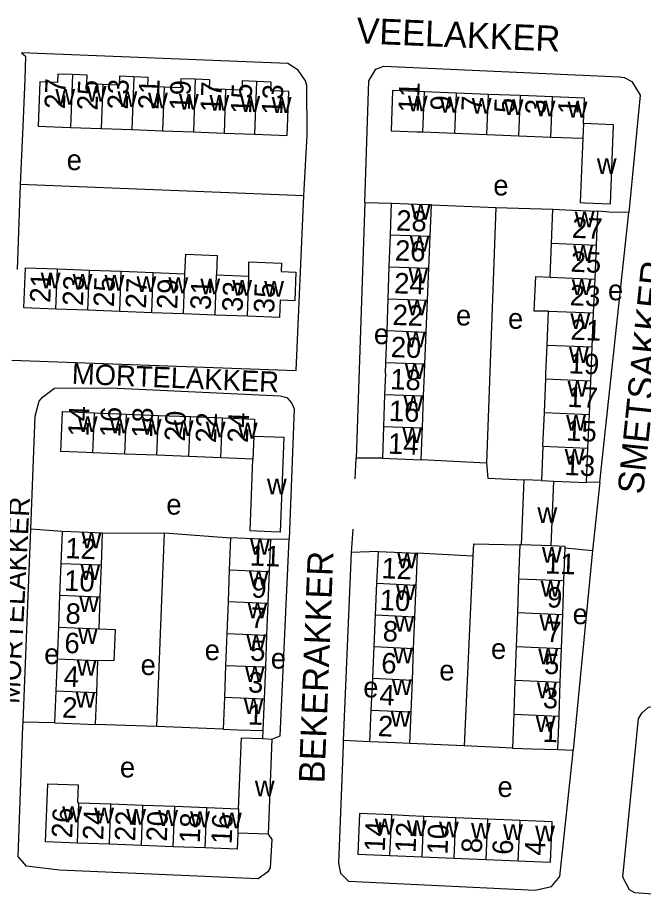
# Model space of a CAD drawing. Extents: x 159675 to 162108, y 386471 to 388472.
# Drawn here: x 161674.3 to 161796.3, y 386647.1 to 386819.4 of the extents above; entities that cross this region are included whole.
import ezdxf

# ---------------------------------------------------------------- set-up
doc = ezdxf.new("R2010")
doc.units = 0
for name, color, linetype in [('BLT_Basislijn', 7, 'Continuous'), ('BLT_Bebouwing', 7, 'Continuous'), ('BLT_Centroide', 7, 'Continuous'), ('BLT_Huisnummer', 7, 'Continuous'), ('BLT_Huisnummer_ tussenligend', 7, 'Continuous'), ('BLT_Onderverdeling_panden', 7, 'Continuous'), ('BLT_Straatnaam', 7, 'Continuous'), ('BLT_Straatnaam_verkleind', 7, 'Continuous')]:
    doc.layers.add(name, color=color, linetype=linetype)

msp = doc.modelspace()

# ---------------------------------------------------------------- linework, layer by layer
at = {"layer": 'BLT_Basislijn'}
for p, q in [((161674.76, 386786.84), (161674.16, 386770.28)), ((161730.1, 386784.65), (161674.76, 386786.84)), ((161741.96, 386783.39), (161740.29, 386733.45)), ((161741.96, 386783.39), (161747.2, 386783.26)), ((161754.96, 386782.93), (161767.51, 386782.36)), ((161767.51, 386782.36), (161765.73, 386732.49)), ((161767.51, 386782.36), (161778.66, 386782.03)), ((161787.79, 386728.78), (161793.47, 386781.38)), ((161740.12, 386729.42), (161740.29, 386733.45)), ((161745.39, 386733.42), (161740.29, 386733.45)), ((161765.73, 386732.49), (161752.95, 386733.14)), ((161787.79, 386728.78), (161785.21, 386728.67)), ((161787.79, 386728.78), (161786.4, 386715.45)), ((161675.32, 386681.93), (161676.8, 386719.59)), ((161682.94, 386719.14), (161676.8, 386719.59)), ((161739.66, 386719.57), (161739.32, 386715.05)), ((161690.77, 386718.83), (161702.9, 386718.89)), ((161701.43, 386681.04), (161702.9, 386718.89)), ((161702.9, 386718.89), (161715.77, 386717.89)), ((161727.24, 386717.62), (161723.65, 386717.55)), ((161763.16, 386716.75), (161763.05, 386714.32)), ((161763.16, 386716.75), (161772.24, 386716.52)), ((161739.32, 386715.05), (161737.76, 386678.31)), ((161744.61, 386715.21), (161739.32, 386715.05)), ((161763.05, 386714.32), (161752.24, 386714.88)), ((161763.05, 386714.32), (161761.38, 386677.29)), ((161781.06, 386715.97), (161786.4, 386715.45)), ((161786.4, 386715.45), (161782.6, 386676.43)), ((161681.46, 386681.8), (161675.32, 386681.93)), ((161701.43, 386681.04), (161689.4, 386681.49)), ((161714.34, 386680.56), (161701.43, 386681.04)), ((161722.06, 386678.7), (161722.13, 386680.26)), ((161742.97, 386678.11), (161737.76, 386678.31)), ((161761.38, 386677.29), (161750.77, 386677.77)), ((161770.77, 386676.86), (161761.38, 386677.29)), ((161779.62, 386676.58), (161782.6, 386676.43))]:
    msp.add_line(p, q, dxfattribs=at)
for points in [[(161675.01, 386812.57), (161675.81, 386811.93), (161675.65, 386807.46), (161675.24, 386798.29), (161674.76, 386786.84)], [(161730.68, 386806.17), (161730.4, 386807.09), (161729, 386809.22), (161726.95, 386810.5), (161675.01, 386812.57)], [(161742.73, 386807.12), (161744.12, 386809.38), (161745.65, 386809.94), (161791.64, 386807.87), (161792.56, 386807.76), (161794.05, 386806.99), (161795.68, 386804.32)], [(161730.1, 386784.65), (161730.72, 386796.47), (161730.68, 386806.17)], [(161741.96, 386783.39), (161742.73, 386807.12)], [(161795.68, 386804.32), (161793.47, 386781.38)], [(161673.12, 386752.56), (161728.61, 386750.56), (161730.1, 386784.65)], [(161793.47, 386781.38), (161789.61, 386781.5), (161787.44, 386781.66)], [(161676.8, 386719.59), (161677.68, 386741.68), (161678.48, 386744.55), (161679.09, 386745.37), (161681.41, 386747.12), (161692.37, 386747.19), (161725.49, 386745.61), (161726.79, 386745.31), (161727.7, 386744.23), (161728.18, 386743.08), (161727.24, 386717.62)], [(161765.73, 386732.49), (161765.98, 386729.53), (161772.97, 386729.2)], [(161723.83, 386678.63), (161725.48, 386679.25), (161727.24, 386717.62)], [(161805.09, 386647.8), (161794.63, 386648.61), (161793.59, 386649.22), (161792.32, 386651.64), (161795.33, 386682.63), (161796.09, 386683.77), (161797.33, 386684.86), (161800.07, 386685.28), (161806.04, 386685.31), (161841.87, 386684), (161847.97, 386683.27), (161849.56, 386681.29), (161849.86, 386679.53), (161849.6, 386649.72), (161849.24, 386648.24), (161847.72, 386646.55), (161844.95, 386646.25), (161810.4, 386647.55)], [(161723.12, 386660.05), (161723.86, 386659.02), (161723.51, 386653.49), (161723.04, 386652.7), (161721.16, 386651.35), (161682.44, 386653.01), (161675.97, 386653.81), (161674.35, 386655.72), (161675.28, 386681.05), (161675.32, 386681.93)], [(161737.76, 386678.31), (161737.73, 386677.52), (161736.81, 386654.37), (161737.21, 386652.44), (161738.8, 386650.88), (161775.17, 386649.12), (161778.39, 386649.83), (161780.04, 386651.8), (161782.52, 386675.55), (161782.6, 386676.43)]]:
    msp.add_lwpolyline(points, dxfattribs=at)
at = {"layer": 'BLT_Bebouwing'}
for p, q in [((161759.86, 386804.72), (161753.63, 386804.97)), ((161766.09, 386804.47), (161759.86, 386804.72)), ((161772.32, 386804.23), (161766.09, 386804.47)), ((161778.56, 386803.98), (161772.32, 386804.23)), ((161684.55, 386798.02), (161690.56, 386797.8)), ((161690.56, 386797.8), (161696.53, 386797.58)), ((161696.53, 386797.58), (161702.53, 386797.35)), ((161702.53, 386797.35), (161708.53, 386797.13)), ((161708.53, 386797.13), (161714.51, 386796.91)), ((161753.32, 386797.13), (161759.55, 386796.88)), ((161714.51, 386796.91), (161720.48, 386796.69)), ((161759.55, 386796.88), (161765.78, 386796.64)), ((161765.78, 386796.64), (161772.01, 386796.39)), ((161772.01, 386796.39), (161778.24, 386796.14)), ((161778.24, 386796.14), (161784.47, 386795.9)), ((161746.98, 386777.04), (161747.2, 386783.26)), ((161754.71, 386776.76), (161754.96, 386782.93)), ((161778.38, 386775.41), (161778.66, 386782.03)), ((161787.16, 386775.04), (161787.44, 386781.66)), ((161746.75, 386770.81), (161746.98, 386777.04)), ((161754.46, 386770.53), (161754.71, 386776.76)), ((161778.1, 386768.79), (161778.38, 386775.41)), ((161786.89, 386768.42), (161787.16, 386775.04)), ((161682.01, 386770.4), (161688.24, 386770.16)), ((161688.24, 386770.16), (161694.47, 386769.93)), ((161694.47, 386769.93), (161700.69, 386769.69)), ((161700.69, 386769.69), (161706.87, 386769.46)), ((161746.52, 386764.58), (161746.75, 386770.81)), ((161754.21, 386764.3), (161754.46, 386770.53)), ((161713.05, 386769.23), (161719.37, 386768.99)), ((161786.61, 386761.8), (161786.89, 386768.42)), ((161746.3, 386758.35), (161746.52, 386764.58)), ((161753.96, 386758.07), (161754.21, 386764.3)), ((161681.72, 386762.55), (161675.49, 386762.78)), ((161687.94, 386762.31), (161681.72, 386762.55)), ((161694.17, 386762.08), (161687.94, 386762.31)), ((161700.4, 386761.85), (161694.17, 386762.08)), ((161706.58, 386761.61), (161700.4, 386761.85)), ((161712.76, 386761.38), (161706.58, 386761.61)), ((161719.08, 386761.14), (161712.76, 386761.38)), ((161777.55, 386755.54), (161777.82, 386762.17)), ((161786.33, 386755.17), (161786.61, 386761.8)), ((161746.07, 386752.12), (161746.3, 386758.35)), ((161753.71, 386751.84), (161753.96, 386758.07)), ((161777.31, 386750), (161777.55, 386755.54)), ((161786.11, 386750), (161786.33, 386755.17)), ((161745.99, 386750), (161746.07, 386752.12)), ((161753.63, 386750), (161753.71, 386751.84)), ((161745.99, 386750), (161745.84, 386745.89)), ((161753.45, 386745.61), (161753.63, 386750)), ((161776.99, 386742.37), (161777.27, 386748.92)), ((161777.27, 386748.92), (161777.31, 386750)), ((161786.05, 386748.55), (161786.11, 386750)), ((161785.77, 386742), (161786.05, 386748.55)), ((161745.84, 386745.89), (161745.62, 386739.66)), ((161753.2, 386739.38), (161753.45, 386745.61)), ((161689.26, 386742.31), (161695.5, 386742.06)), ((161695.5, 386742.06), (161701.74, 386741.81)), ((161776.71, 386735.79), (161776.99, 386742.37)), ((161785.5, 386735.42), (161785.77, 386742)), ((161701.74, 386741.81), (161707.98, 386741.56)), ((161707.98, 386741.56), (161714.23, 386741.31)), ((161745.62, 386739.66), (161745.39, 386733.42)), ((161785.21, 386728.67), (161785.5, 386735.42)), ((161695.19, 386734.26), (161688.94, 386734.51)), ((161701.43, 386734.01), (161695.19, 386734.26)), ((161713.91, 386733.51), (161707.62, 386733.76)), ((161720.15, 386733.26), (161713.91, 386733.51)), ((161745.39, 386733.42), (161752.95, 386733.14)), ((161772.97, 386729.2), (161772.44, 386716.51)), ((161776.43, 386729.06), (161772.97, 386729.2)), ((161778.32, 386716.35), (161778.85, 386728.93)), ((161778.85, 386728.93), (161785.21, 386728.67)), ((161682.94, 386719.14), (161682.69, 386712.91)), ((161690.77, 386718.83), (161690.54, 386712.6)), ((161715.77, 386717.89), (161715.53, 386711.67)), ((161723.4, 386711.36), (161723.65, 386717.55)), ((161772.44, 386716.51), (161772.24, 386716.52)), ((161744.33, 386709.03), (161744.61, 386715.21)), ((161744.61, 386715.21), (161752.24, 386714.88)), ((161780.82, 386709.54), (161781.06, 386715.97)), ((161682.69, 386712.91), (161682.44, 386706.69)), ((161690.54, 386712.6), (161690.31, 386706.38)), ((161715.53, 386711.67), (161715.29, 386705.45)), ((161723.15, 386705.14), (161723.4, 386711.36)), ((161771.98, 386709.91), (161771.74, 386703.3)), ((161780.58, 386702.93), (161780.82, 386709.54)), ((161744.06, 386702.84), (161744.33, 386709.03)), ((161751.74, 386702.51), (161751.99, 386708.69)), ((161682.44, 386706.69), (161682.2, 386700.47)), ((161690.31, 386706.38), (161690.09, 386700.16)), ((161715.29, 386705.45), (161715.06, 386699.23)), ((161722.89, 386698.92), (161723.15, 386705.14)), ((161743.79, 386696.66), (161744.06, 386702.84)), ((161751.5, 386696.32), (161751.74, 386702.51)), ((161771.74, 386703.3), (161771.49, 386696.7)), ((161780.34, 386696.33), (161780.58, 386702.93)), ((161682.2, 386700.47), (161681.95, 386694.25)), ((161715.06, 386699.23), (161714.82, 386693.01)), ((161722.64, 386692.7), (161722.89, 386698.92)), ((161743.52, 386690.48), (161743.79, 386696.66)), ((161751.26, 386690.13), (161751.5, 386696.32)), ((161771.49, 386696.7), (161771.26, 386690.09)), ((161780.1, 386689.72), (161780.34, 386696.33)), ((161681.95, 386694.25), (161681.7, 386688.03)), ((161689.86, 386693.93), (161689.63, 386687.71)), ((161714.82, 386693.01), (161714.58, 386686.79)), ((161722.38, 386686.49), (161722.64, 386692.7)), ((161743.24, 386684.29), (161743.52, 386690.48)), ((161751.02, 386683.95), (161751.26, 386690.13)), ((161771.26, 386690.09), (161771.02, 386683.48)), ((161779.86, 386683.11), (161780.1, 386689.72)), ((161681.7, 386688.03), (161681.46, 386681.8)), ((161689.63, 386687.71), (161689.4, 386681.49)), ((161714.58, 386686.79), (161714.34, 386680.56)), ((161722.13, 386680.26), (161722.38, 386686.49)), ((161742.97, 386678.11), (161743.24, 386684.29)), ((161750.77, 386677.77), (161751.02, 386683.95)), ((161771.02, 386683.48), (161770.77, 386676.86)), ((161779.62, 386676.58), (161779.86, 386683.11)), ((161722.06, 386678.7), (161723.83, 386678.63)), ((161723.83, 386678.63), (161723.12, 386660.05)), ((161686.22, 386666.2), (161692.46, 386665.96)), ((161692.46, 386665.96), (161698.69, 386665.73)), ((161698.69, 386665.73), (161704.92, 386665.49)), ((161704.92, 386665.49), (161711.16, 386665.25)), ((161711.16, 386665.25), (161717.36, 386665.01)), ((161759.74, 386663.26), (161753.48, 386663.53)), ((161765.99, 386662.99), (161759.74, 386663.26)), ((161772.25, 386662.73), (161765.99, 386662.99)), ((161723.12, 386660.05), (161717.2, 386660.27)), ((161692.15, 386658.08), (161685.92, 386658.32)), ((161698.39, 386657.84), (161692.15, 386658.08)), ((161704.62, 386657.6), (161698.39, 386657.84)), ((161710.85, 386657.36), (161704.62, 386657.6)), ((161746.88, 386655.9), (161753.14, 386655.64)), ((161753.14, 386655.64), (161759.4, 386655.37)), ((161759.4, 386655.37), (161765.65, 386655.1)), ((161765.65, 386655.1), (161771.91, 386654.83))]:
    msp.add_line(p, q, dxfattribs=at)
for points in [[(161684.93, 386808.34), (161682.07, 386808.44), (161682, 386806.78), (161678.61, 386806.9), (161678.28, 386798.25), (161684.55, 386798.02)], [(161690.88, 386806.39), (161687.73, 386806.51), (161687.8, 386808.23), (161684.93, 386808.34)], [(161696.91, 386807.88), (161694.09, 386807.99), (161694.03, 386806.28), (161690.88, 386806.39)], [(161702.85, 386805.86), (161699.67, 386805.98), (161699.74, 386807.78), (161696.91, 386807.88)], [(161708.91, 386807.42), (161706.09, 386807.53), (161706.02, 386805.74), (161702.85, 386805.86)], [(161714.82, 386805.41), (161711.67, 386805.52), (161711.74, 386807.32), (161708.91, 386807.42)], [(161720.86, 386806.97), (161718.04, 386807.08), (161717.98, 386805.29), (161714.82, 386805.41)], [(161720.48, 386796.69), (161726.83, 386796.45), (161727.15, 386805.03), (161723.62, 386805.16), (161723.68, 386806.87), (161720.86, 386806.97)], [(161753.63, 386804.97), (161747.4, 386805.21), (161747.09, 386797.37), (161752.09, 386797.18), (161753.32, 386797.13)], [(161784.61, 386798.75), (161784.8, 386803.73), (161778.56, 386803.98)], [(161784.47, 386795.9), (161783.98, 386783.33), (161784.88, 386783.3), (161789.88, 386783.1), (161790.49, 386798.52), (161784.61, 386798.75)], [(161747.2, 386783.26), (161752.2, 386783.05), (161754.85, 386782.94), (161754.96, 386782.93)], [(161778.66, 386782.03), (161782.45, 386781.87), (161787.44, 386781.66)], [(161706.87, 386769.46), (161707.04, 386773.25), (161713.2, 386773.02), (161713.05, 386769.23)], [(161719.37, 386768.99), (161719.34, 386771.77), (161725.7, 386771.53), (161725.64, 386769.87), (161728.54, 386769.76), (161728.33, 386764.19), (161725.43, 386764.3), (161725.3, 386760.91), (161719.08, 386761.14)], [(161675.49, 386762.78), (161675.79, 386770.63), (161682.01, 386770.4)], [(161777.82, 386762.17), (161775.02, 386762.15), (161775.31, 386768.9), (161778.1, 386768.79)], [(161688.94, 386734.51), (161687.7, 386734.56), (161682.7, 386734.76), (161683.02, 386742.56), (161689.26, 386742.31)], [(161714.23, 386741.31), (161720.48, 386741.06), (161720.34, 386737.75)], [(161752.95, 386733.14), (161753.15, 386738.14), (161753.2, 386739.38)], [(161720.34, 386737.75), (161726.17, 386737.52), (161725.43, 386719.01), (161723.72, 386719.08)], [(161776.71, 386735.79), (161776.64, 386734.05), (161776.43, 386729.06)], [(161707.62, 386733.76), (161701.43, 386734.01)], [(161723.72, 386719.08), (161719.59, 386719.24), (161720.15, 386733.26)], [(161690.77, 386718.83), (161687.93, 386718.94), (161682.94, 386719.14)], [(161723.65, 386717.55), (161718.66, 386717.76), (161715.77, 386717.89)], [(161772.24, 386716.52), (161772.04, 386711.6), (161771.98, 386709.91)], [(161781.06, 386715.97), (161781.07, 386716.23), (161778.32, 386716.35)], [(161751.99, 386708.69), (161752.03, 386709.89), (161752.24, 386714.88)], [(161690.09, 386700.16), (161693.26, 386700.03), (161693.02, 386693.87), (161689.86, 386693.93)], [(161681.46, 386681.8), (161686.45, 386681.61), (161689.4, 386681.49)], [(161714.34, 386680.56), (161717.13, 386680.45), (161722.13, 386680.26)], [(161717.36, 386665.01), (161717.9, 386678.86), (161722.06, 386678.7)], [(161750.77, 386677.77), (161747.97, 386677.89), (161742.97, 386678.11)], [(161770.77, 386676.86), (161774.62, 386676.74), (161779.62, 386676.58)], [(161685.92, 386658.32), (161679.69, 386658.55), (161680.12, 386669.89), (161686.04, 386669.66), (161685.91, 386666.22), (161686.22, 386666.2)], [(161747.22, 386663.8), (161740.95, 386664.09), (161740.62, 386656.17), (161746.88, 386655.9)], [(161753.48, 386663.53), (161750.57, 386663.65), (161747.22, 386663.8)], [(161771.91, 386654.83), (161778.17, 386654.56), (161778.5, 386662.46), (161772.25, 386662.73)], [(161717.2, 386660.27), (161717.08, 386657.12), (161710.85, 386657.36)]]:
    msp.add_lwpolyline(points, dxfattribs=at)
at = {"layer": 'BLT_Onderverdeling_panden'}
for p, q in [((161684.93, 386808.34), (161684.55, 386798.02)), ((161696.91, 386807.88), (161696.53, 386797.58)), ((161708.91, 386807.42), (161708.53, 386797.13)), ((161690.88, 386806.39), (161690.56, 386797.8)), ((161702.85, 386805.86), (161702.53, 386797.35)), ((161720.86, 386806.97), (161720.48, 386796.69)), ((161714.82, 386805.41), (161714.51, 386796.91)), ((161753.32, 386797.13), (161753.63, 386804.97)), ((161759.55, 386796.88), (161759.86, 386804.72)), ((161765.78, 386796.64), (161766.09, 386804.47)), ((161772.01, 386796.39), (161772.32, 386804.23)), ((161778.24, 386796.14), (161778.56, 386803.98)), ((161784.61, 386798.75), (161784.47, 386795.9)), ((161746.98, 386777.04), (161754.71, 386776.76)), ((161778.38, 386775.41), (161787.16, 386775.04)), ((161681.72, 386762.55), (161682.01, 386770.4)), ((161687.94, 386762.31), (161688.24, 386770.16)), ((161694.17, 386762.08), (161694.47, 386769.93)), ((161700.4, 386761.85), (161700.69, 386769.69)), ((161706.58, 386761.61), (161706.87, 386769.46)), ((161746.75, 386770.81), (161754.46, 386770.53)), ((161712.76, 386761.38), (161713.05, 386769.23)), ((161719.08, 386761.14), (161719.37, 386768.99)), ((161778.1, 386768.79), (161786.89, 386768.42)), ((161746.52, 386764.58), (161754.21, 386764.3)), ((161777.82, 386762.17), (161786.61, 386761.8)), ((161746.3, 386758.35), (161753.96, 386758.07)), ((161777.55, 386755.54), (161786.33, 386755.17)), ((161746.07, 386752.12), (161753.71, 386751.84)), ((161777.27, 386748.92), (161786.05, 386748.55)), ((161745.84, 386745.89), (161753.45, 386745.61)), ((161688.94, 386734.51), (161689.26, 386742.31)), ((161695.19, 386734.26), (161695.5, 386742.06)), ((161776.99, 386742.37), (161785.77, 386742)), ((161701.43, 386734.01), (161701.74, 386741.81)), ((161707.62, 386733.76), (161707.98, 386741.56)), ((161713.91, 386733.51), (161714.23, 386741.31)), ((161745.62, 386739.66), (161753.2, 386739.38)), ((161720.34, 386737.75), (161720.15, 386733.26)), ((161776.71, 386735.79), (161785.5, 386735.42)), ((161776.43, 386729.06), (161778.85, 386728.93)), ((161778.32, 386716.35), (161772.44, 386716.51)), ((161682.69, 386712.91), (161690.54, 386712.6)), ((161715.53, 386711.67), (161723.4, 386711.36)), ((161771.98, 386709.91), (161780.82, 386709.54)), ((161744.33, 386709.03), (161751.99, 386708.69)), ((161682.44, 386706.69), (161690.31, 386706.38)), ((161715.29, 386705.45), (161723.15, 386705.14)), ((161744.06, 386702.84), (161751.74, 386702.51)), ((161771.74, 386703.3), (161780.58, 386702.93)), ((161682.2, 386700.47), (161690.09, 386700.16)), ((161715.06, 386699.23), (161722.89, 386698.92)), ((161743.79, 386696.66), (161751.5, 386696.32)), ((161771.49, 386696.7), (161780.34, 386696.33)), ((161681.95, 386694.25), (161689.86, 386693.93)), ((161714.82, 386693.01), (161722.64, 386692.7)), ((161743.52, 386690.48), (161751.26, 386690.13)), ((161771.26, 386690.09), (161780.1, 386689.72)), ((161681.7, 386688.03), (161689.63, 386687.71)), ((161714.58, 386686.79), (161722.38, 386686.49)), ((161743.24, 386684.29), (161751.02, 386683.95)), ((161771.02, 386683.48), (161779.86, 386683.11)), ((161685.92, 386658.32), (161686.22, 386666.2)), ((161692.15, 386658.08), (161692.46, 386665.96)), ((161698.39, 386657.84), (161698.69, 386665.73)), ((161704.62, 386657.6), (161704.92, 386665.49)), ((161710.85, 386657.36), (161711.16, 386665.25)), ((161717.36, 386665.01), (161717.2, 386660.27)), ((161746.88, 386655.9), (161747.22, 386663.8)), ((161753.14, 386655.64), (161753.48, 386663.53)), ((161759.4, 386655.37), (161759.74, 386663.26)), ((161765.65, 386655.1), (161765.99, 386662.99)), ((161771.91, 386654.83), (161772.25, 386662.73))]:
    msp.add_line(p, q, dxfattribs=at)

# ---------------------------------------------------------------- texts
at = {"layer": 'BLT_Centroide'}
for s, p in [('w', (161687.72, 386803.06)), ('w', (161681.61, 386802.45)), ('w', (161693.73, 386801.98)), ('w', (161699.69, 386801.72)), ('w', (161705.72, 386801.48)), ('w', (161711.67, 386801.27)), ('w', (161717.69, 386801.05)), ('w', (161723.81, 386800.86)), ('w', (161750.36, 386801.17)), ('w', (161756.59, 386800.92)), ('w', (161762.83, 386800.67)), ('w', (161769.05, 386800.42)), ('w', (161775.28, 386800.19)), ('w', (161781.53, 386799.94)), ('e', (161683.82, 386789.68)), ('w', (161787.23, 386788.94)), ('e', (161767.04, 386784.73)), ('w', (161750.96, 386780)), ('w', (161782.91, 386778.53)), ('w', (161750.73, 386773.78)), ('w', (161782.63, 386771.91)), ('w', (161678.75, 386766.59)), ('w', (161750.48, 386767.56)), ('w', (161684.98, 386766.36)), ('w', (161691.2, 386766.12)), ('w', (161697.44, 386765.89)), ('w', (161703.66, 386765.66)), ('w', (161709.89, 386765.42)), ('w', (161716.11, 386765.19)), ('w', (161722.34, 386764.95)), ('w', (161782.35, 386765.28)), ('e', (161789.4, 386764.27)), ('w', (161750.25, 386761.31)), ('e', (161759.75, 386759.35)), ('e', (161769.9, 386758.71)), ('w', (161782.07, 386758.66)), ('e', (161743.74, 386755.7)), ('w', (161750.01, 386755.09)), ('w', (161781.8, 386752.06)), ('w', (161749.77, 386748.88)), ('w', (161781.52, 386745.44)), ('w', (161749.52, 386742.62)), ('w', (161781.24, 386738.81)), ('w', (161685.98, 386738.53)), ('w', (161692.22, 386738.28)), ('w', (161698.47, 386738.03)), ('w', (161704.7, 386737.78)), ('w', (161710.95, 386737.53)), ('w', (161717.19, 386737.28)), ('w', (161749.29, 386736.41)), ('w', (161780.96, 386732.19)), ('w', (161722.88, 386726.39)), ('e', (161703.25, 386722.43)), ('w', (161775.64, 386720.77)), ('w', (161686.73, 386715.88)), ('w', (161719.59, 386714.62)), ('w', (161776.52, 386713.03)), ('w', (161748.29, 386711.94)), ('w', (161686.5, 386709.66)), ('w', (161719.34, 386708.41)), ('w', (161776.27, 386706.44)), ('w', (161748.03, 386705.78)), ('w', (161686.26, 386703.44)), ('w', (161719.1, 386702.19)), ('e', (161782.51, 386701.04)), ('w', (161747.77, 386699.59)), ('w', (161776.04, 386699.81)), ('w', (161686.02, 386697.19)), ('w', (161718.85, 386695.97)), ('e', (161710.74, 386694.01)), ('e', (161766.58, 386694.26)), ('e', (161679.43, 386693.25)), ('e', (161723.63, 386692.37)), ('w', (161747.52, 386693.41)), ('w', (161775.8, 386693.22)), ('w', (161685.78, 386690.97)), ('e', (161698.24, 386691.11)), ('w', (161718.6, 386689.75)), ('e', (161756.5, 386690.05)), ('w', (161747.26, 386687.22)), ('e', (161741.67, 386686.75)), ('w', (161775.55, 386686.59)), ('w', (161685.55, 386684.75)), ('w', (161718.36, 386683.53)), ('w', (161747, 386681.03)), ('w', (161775.32, 386680.03)), ('e', (161694.2, 386671.14)), ('w', (161720.52, 386667.45)), ('e', (161767.86, 386667.32)), ('w', (161682.95, 386662.39)), ('w', (161689.19, 386662.14)), ('w', (161695.42, 386661.89)), ('w', (161701.66, 386661.67)), ('w', (161707.89, 386661.42)), ('w', (161714.11, 386661.17)), ('w', (161743.92, 386659.98)), ('w', (161750.17, 386659.7)), ('w', (161756.44, 386659.45)), ('w', (161762.69, 386659.17)), ('w', (161768.95, 386658.92)), ('w', (161775.2, 386658.64))]:
    msp.add_text(s, height=4, dxfattribs=at).set_placement(p)
at = {"layer": 'BLT_Huisnummer'}
for s, rotation, p in [('27', 87.8713, (161683.47, 386801.55)), ('21', 87.8713, (161701.75, 386801.44)), ('17', 87.8713, (161713.88, 386800.94)), ('13', 87.8713, (161725.87, 386800.42)), ('11', 87.7348, (161752.48, 386800.87)), ('5', 87.7348, (161771.19, 386800.75)), ('1', 87.7348, (161783.63, 386800.53)), ('28', 357.8795, (161748.04, 386777.9)), ('27', 357.5901, (161782.31, 386776.48)), ('21', 87.8473, (161680.62, 386763.72)), ('25', 87.8473, (161693.02, 386762.91)), ('29', 87.8473, (161705.37, 386762.48)), ('35', 87.8473, (161724.28, 386761.7)), ('22', 357.8795, (161747.33, 386759.47)), ('21', 357.5901, (161782.06, 386756.6)), ('18', 357.8795, (161746.88, 386746.91)), ('17', 357.5901, (161781.43, 386743.47)), ('14', 87.7032, (161688.06, 386737.62)), ('18', 87.7032, (161700.48, 386737.35)), ('24', 87.7032, (161719.16, 386736.38)), ('14', 357.8795, (161746.44, 386734.34)), ('13', 357.5901, (161780.87, 386730.18)), ('12', 357.7996, (161683.5, 386713.94)), ('11', 357.7534, (161719.49, 386712.51)), ('11', 358.1775, (161777.07, 386710.95)), ('12', 357.4786, (161745.16, 386710.03)), ('6', 357.7996, (161683.32, 386695.43)), ('5', 357.7534, (161719.55, 386693.93)), ('6', 357.4786, (161745.12, 386691.49)), ('5', 358.1775, (161776.89, 386691.34)), ('2', 357.7996, (161682.88, 386682.82)), ('1', 357.7534, (161719.1, 386681.48)), ('2', 357.4786, (161744.44, 386679.21)), ('1', 358.1775, (161776.61, 386678.09)), ('26', 87.8002, (161684.87, 386659.24)), ('20', 87.8002, (161703.34, 386658.55)), ('16', 87.8002, (161716, 386658.06)), ('14', 87.6439, (161745.85, 386656.57)), ('8', 87.6439, (161764.78, 386656.31)), ('4', 87.6439, (161777.12, 386655.8))]:
    msp.add_text(s, height=4, rotation=rotation, dxfattribs=at).set_placement(p)
at = {"layer": 'BLT_Huisnummer_ tussenligend'}
for s, rotation, p in [('25', 87.8713, (161689.83, 386801.28)), ('23', 87.8713, (161695.73, 386801.44)), ('19', 87.8713, (161707.86, 386801.23)), ('15', 87.8713, (161719.81, 386800.58)), ('9', 87.7348, (161758.72, 386801.22)), ('7', 87.7348, (161764.78, 386801.13)), ('3', 87.7348, (161777.22, 386800.49)), ('26', 357.8795, (161747.8, 386772.04)), ('25', 357.5901, (161782.06, 386769.86)), ('24', 357.8795, (161747.63, 386765.65)), ('23', 87.8473, (161686.99, 386763.11)), ('27', 87.8473, (161699.28, 386762.6)), ('31', 87.8473, (161711.9, 386762.33)), ('33', 87.8473, (161718.11, 386761.96)), ('23', 357.5901, (161781.89, 386763.3)), ('20', 357.8795, (161746.98, 386753.19)), ('19', 357.5901, (161781.68, 386750.02)), ('16', 357.8795, (161746.61, 386740.73)), ('16', 87.7032, (161694.28, 386737.46)), ('20', 87.7032, (161706.88, 386736.68)), ('22', 87.7032, (161712.94, 386736.36)), ('15', 357.5901, (161781.2, 386736.9)), ('10', 357.7996, (161683.26, 386707.6)), ('9', 357.7534, (161719.79, 386706.25)), ('10', 357.4786, (161744.81, 386703.83)), ('9', 358.1775, (161777.46, 386704.33)), ('8', 357.7996, (161683.53, 386701.18)), ('7', 357.7534, (161719.62, 386700.35)), ('8', 357.4786, (161745.41, 386697.73)), ('7', 358.1775, (161777.29, 386697.61)), ('4', 357.7996, (161683.2, 386688.89)), ('3', 357.7534, (161719.14, 386687.73)), ('4', 357.4786, (161744.75, 386685.28)), ('3', 358.1775, (161776.65, 386684.66)), ('24', 87.8002, (161690.93, 386658.84)), ('22', 87.8002, (161697.16, 386658.61)), ('18', 87.8002, (161709.78, 386658.24)), ('12', 87.6439, (161751.87, 386656.37)), ('10', 87.6439, (161758.09, 386656.03)), ('6', 87.6439, (161770.82, 386655.97))]:
    msp.add_text(s, height=4, rotation=rotation, dxfattribs=at).set_placement(p)
at = {"layer": 'BLT_Straatnaam'}
for s, rotation, p in [('VEELAKKER', 357.6335, (161740.27, 386814.45)), ('SMETSAKKER', 84.0965, (161796.24, 386726.28)), ('BEKERAKKER', 87.7507, (161734.08, 386669.92))]:
    msp.add_text(s, height=5, rotation=rotation, dxfattribs=at).set_placement(p)
at = {"layer": 'BLT_Straatnaam_verkleind'}
for rotation, p in [(357.6146, (161684.76, 386747.99)), (87.0352, (161674.57, 386685.43))]:
    msp.add_text('MORTELAKKER', height=4, rotation=rotation, dxfattribs=at).set_placement(p)

doc.saveas('drawing.dxf')
